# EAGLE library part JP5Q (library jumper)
JUMPER
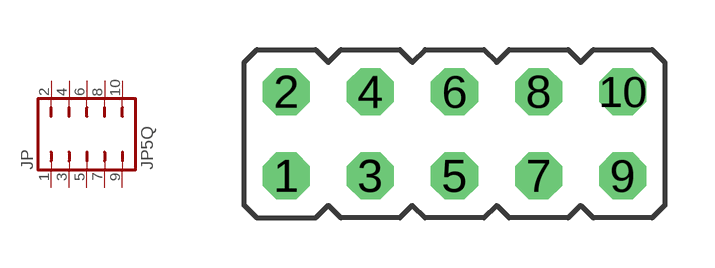
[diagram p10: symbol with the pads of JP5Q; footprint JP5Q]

Designator prefix JP

## JP5Q  [JP5Q]
1  1  pas
2  2  pas
3  3  pas
4  4  pas
5  5  pas
6  6  pas
7  7  pas
8  8  pas
9  9  pas
10  10  pas

## Footprint JP5Q (pad centres in mm)
JUMPER
drill 0.914 octagon: 1 -5.08,-1.27; 2 -5.08,1.27; 3 -2.54,-1.27; 4 -2.54,1.27; 5 0,-1.27; 6 0,1.27; 7 2.54,-1.27; 8 2.54,1.27; 9 5.08,-1.27; 10 5.08,1.27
